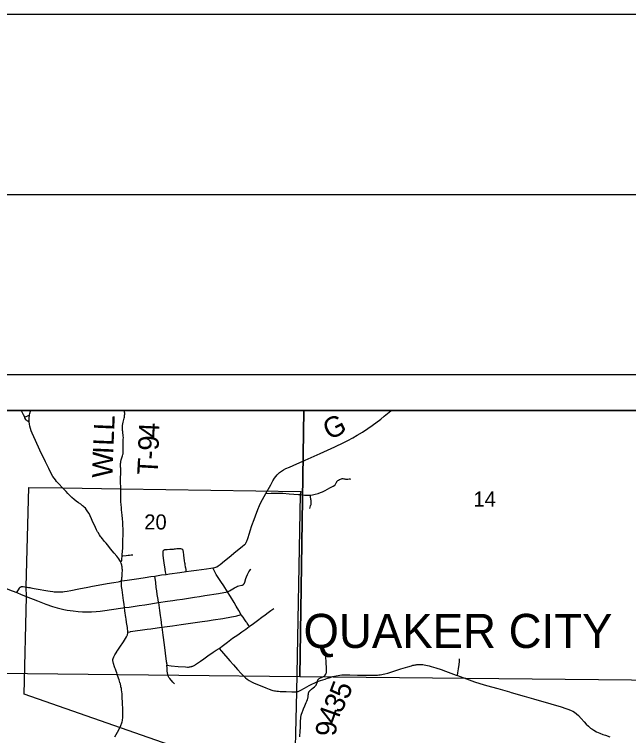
# Model space of a CAD drawing. Extents: x 0 to 34, y 0 to 22.
# Drawn here: x 3.378 to 5.085, y 19.997 to 22 of the extents above; entities that cross this region are included whole.
import ezdxf

# ---------------------------------------------------------------- set-up
doc = ezdxf.new("R2010")
doc.units = 0
for name, color, linetype in [('GM_X_City_Street', 7, 'Continuous'), ('GM_X_Corporation', 7, 'Continuous'), ('GM_X_Corporation_Text', 7, 'Continuous'), ('GM_X_County_Road', 7, 'Continuous'), ('GM_X_County_Road_Text', 7, 'Continuous'), ('GM_X_Section_Text', 7, 'Continuous'), ('GM_X_State_Route', 7, 'Continuous'), ('GM_X_Township_Road', 7, 'Continuous'), ('GM_X_Township_Road_Text', 7, 'Continuous'), ('GM_X_Township_Text', 7, 'Continuous'), ('SH_Border', 7, 'Continuous'), ('SH_Cut_Line', 7, 'Continuous'), ('SH_Data', 7, 'Continuous')]:
    doc.layers.add(name, color=color, linetype=linetype)

msp = doc.modelspace()

# ---------------------------------------------------------------- linework, layer by layer
at = {"layer": 'GM_X_City_Street'}
for points in [[(3.6736, 20.4785), (3.6744, 20.4795), (3.6749, 20.4801), (3.6753, 20.4807), (3.6757, 20.4812), (3.6762, 20.4823), (3.6765, 20.4832), (3.6767, 20.4842), (3.6769, 20.4857), (3.677, 20.4875), (3.6777, 20.4956), (3.6781, 20.5002), (3.6792, 20.5172), (3.6796, 20.5263), (3.6797, 20.5366), (3.6798, 20.5408), (3.6801, 20.5531), (3.6804, 20.5634), (3.6803, 20.5719), (3.6799, 20.5793), (3.6794, 20.5896), (3.6789, 20.5987), (3.6777, 20.6091), (3.6761, 20.6238), (3.6756, 20.628), (3.6747, 20.641), (3.6744, 20.644), (3.6744, 20.6446), (3.6742, 20.649), (3.6742, 20.6564), (3.6743, 20.6613), (3.6744, 20.6644), (3.6744, 20.6668), (3.6743, 20.6702), (3.6742, 20.6725), (3.6741, 20.6749), (3.6741, 20.6766), (3.6739, 20.6818)], [(3.7687, 20.4399), (3.7873, 20.443), (3.7995, 20.4447), (3.8094, 20.4462), (3.8377, 20.4502), (3.8552, 20.4526), (3.8691, 20.4545), (3.8839, 20.4564), (3.9122, 20.46), (3.9239, 20.4616), (3.9296, 20.4625), (3.9306, 20.4626), (3.9354, 20.4637), (3.9382, 20.4646), (3.9409, 20.4659), (3.9445, 20.4681), (3.9499, 20.4722), (3.9625, 20.4823), (3.975, 20.4925), (3.9939, 20.5078), (4.0113, 20.5216), (4.0179, 20.5273), (4.0192, 20.5286), (4.0203, 20.5299), (4.0211, 20.5309), (4.0217, 20.5319), (4.0224, 20.5333), (4.0232, 20.535), (4.0239, 20.5366), (4.0266, 20.5443), (4.0313, 20.5591), (4.0335, 20.5656), (4.0383, 20.5804), (4.0444, 20.5973), (4.0481, 20.6072), (4.0548, 20.6246), (4.0595, 20.6362), (4.0631, 20.6441), (4.0677, 20.6529), (4.0768, 20.6693)], [(4.0768, 20.6693), (4.0917, 20.6701), (4.1029, 20.6705), (4.1128, 20.6705), (4.124, 20.6699), (4.1413, 20.6686), (4.1673, 20.6665), (4.1727, 20.6661)], [(3.7995, 20.4447), (3.7984, 20.4514), (3.796, 20.4653), (3.7954, 20.4698), (3.7944, 20.4767), (3.7929, 20.4894), (3.7919, 20.4981), (3.7916, 20.5024), (3.7915, 20.504), (3.7915, 20.5056), (3.7915, 20.5067), (3.7916, 20.5079), (3.7918, 20.5087), (3.792, 20.5096), (3.7923, 20.5104), (3.7928, 20.5113), (3.7934, 20.512), (3.794, 20.5125), (3.795, 20.5132), (3.796, 20.5135), (3.7978, 20.5138), (3.8027, 20.514), (3.8102, 20.5142), (3.8151, 20.5146), (3.8201, 20.515), (3.8231, 20.5154), (3.8259, 20.5159), (3.8292, 20.5164), (3.8323, 20.5165), (3.8366, 20.5165), (3.8402, 20.5162), (3.8426, 20.5157), (3.8437, 20.5153), (3.8447, 20.5146), (3.8455, 20.5138), (3.846, 20.5128), (3.8464, 20.5111), (3.847, 20.5061), (3.8477, 20.4991), (3.8491, 20.4884), (3.8498, 20.4841), (3.8503, 20.481), (3.8508, 20.4776), (3.8514, 20.4749), (3.8522, 20.471), (3.8531, 20.466), (3.8537, 20.4627), (3.8544, 20.4579), (3.8548, 20.4555), (3.8552, 20.4526)], [(3.6777, 20.4956), (3.6794, 20.4959), (3.6885, 20.497), (3.6947, 20.4977), (3.6983, 20.4982), (3.7027, 20.4988), (3.7071, 20.4993)], [(4.0308, 20.2999), (4.0284, 20.3036), (4.0247, 20.3092), (4.0237, 20.3107), (4.0223, 20.3127), (4.0182, 20.3188), (4.0135, 20.3254), (4.0088, 20.3319), (4.0078, 20.3334), (4.0071, 20.3345), (4.0017, 20.3443), (3.9946, 20.3566), (3.9887, 20.3661), (3.9783, 20.383), (3.9706, 20.3957), (3.9602, 20.4127), (3.9521, 20.4252), (3.9444, 20.4364), (3.939, 20.4447), (3.9349, 20.4516), (3.933, 20.4555), (3.9313, 20.4589), (3.9296, 20.4625)], [(3.9706, 20.3957), (3.9758, 20.3988), (3.9901, 20.4076), (3.9951, 20.4102), (3.9985, 20.4116), (4.0021, 20.4127), (4.0101, 20.4143), (4.0113, 20.4147), (4.0124, 20.4151), (4.0133, 20.4156), (4.014, 20.416), (4.0148, 20.4166), (4.0154, 20.4172), (4.016, 20.4179), (4.0166, 20.4187), (4.0171, 20.4194), (4.0175, 20.4203), (4.0185, 20.4233), (4.0214, 20.4335), (4.0229, 20.4376), (4.0259, 20.4444), (4.0297, 20.4515), (4.0324, 20.4557), (4.0344, 20.4581), (4.0353, 20.459)], [(3.4115, 20.4095), (3.4141, 20.409), (3.4178, 20.4084), (3.4208, 20.4078), (3.4241, 20.4072), (3.4332, 20.4053), (3.4503, 20.4025), (3.4601, 20.4006), (3.4711, 20.3988), (3.478, 20.3977), (3.4852, 20.3968), (3.4889, 20.3965), (3.4932, 20.3962), (3.498, 20.3959), (3.5025, 20.3959), (3.5056, 20.3958), (3.5093, 20.3961), (3.5131, 20.3963), (3.5173, 20.3968), (3.5247, 20.3979), (3.5351, 20.3998), (3.5576, 20.4045), (3.582, 20.4092), (3.5954, 20.4116), (3.6107, 20.4142), (3.6363, 20.419), (3.6547, 20.422), (3.6669, 20.4242), (3.6699, 20.4249), (3.6758, 20.4263), (3.6846, 20.4277), (3.6916, 20.4286), (3.7241, 20.4335), (3.7419, 20.4363), (3.7573, 20.4384), (3.7687, 20.4399)], [(3.7784, 20.3667), (3.7775, 20.3751), (3.7754, 20.3886), (3.7739, 20.3991), (3.7726, 20.4083), (3.7708, 20.4225), (3.7687, 20.4399)], [(3.7784, 20.3667), (3.8032, 20.37), (3.8186, 20.3724), (3.8297, 20.374), (3.8457, 20.3762), (3.8789, 20.3812), (3.893, 20.3834), (3.9071, 20.3855), (3.9458, 20.3913), (3.9706, 20.3957)], [(3.6934, 20.2844), (3.6999, 20.2853), (3.7011, 20.2855), (3.7475, 20.2923), (3.757, 20.2936), (3.7871, 20.2976), (3.7879, 20.2977), (3.8179, 20.3019), (3.8412, 20.3053), (3.8806, 20.3109), (3.8997, 20.3136), (3.9144, 20.3158), (3.9304, 20.3183), (3.9571, 20.3223), (3.9813, 20.3264), (3.9926, 20.3285), (3.9966, 20.3295), (3.9991, 20.3301), (4.0025, 20.3314), (4.0058, 20.3326), (4.0078, 20.3334)], [(3.9473, 20.239), (3.9593, 20.2481), (3.9702, 20.2564), (3.9846, 20.267), (3.9988, 20.2771), (4.0105, 20.2852), (4.0213, 20.2926), (4.0308, 20.2999), (4.0316, 20.3005), (4.0385, 20.3058), (4.0536, 20.3167), (4.0656, 20.3255), (4.0751, 20.3324), (4.0838, 20.3384), (4.0912, 20.3439), (4.099, 20.35)], [(3.8228, 20.1406), (3.8187, 20.1451), (3.8097, 20.1554), (3.8086, 20.1568), (3.8076, 20.1584), (3.8068, 20.1598), (3.8062, 20.1611), (3.8053, 20.163), (3.8048, 20.1646), (3.8042, 20.167), (3.8036, 20.1694), (3.8032, 20.1718), (3.8029, 20.1743), (3.8024, 20.1797), (3.8024, 20.1845), (3.8022, 20.192)]]:
    msp.add_lwpolyline(points, dxfattribs=at)
at = {"layer": 'GM_X_Corporation'}
for points in [[(4.1826, 20.9), (3.1678, 20.9), (3.1616, 20.1718), (4.1713, 20.1609)], [(5.1978, 20.9), (4.1826, 20.9), (4.1713, 20.1609), (5.1859, 20.1511)], [(4.156, 19.8502), (3.4056, 20.1119), (3.4116, 20.3825), (3.4113, 20.41), (3.4183, 20.6864), (3.5128, 20.6849), (3.6737, 20.6823), (4.1737, 20.6751), (4.1725, 20.6666), (4.1618, 20.1184)]]:
    msp.add_lwpolyline(points, close=True, dxfattribs=at)
at = {"layer": 'GM_X_County_Road'}
msp.add_lwpolyline([(4.0768, 20.6693), (4.0904, 20.6938), (4.0963, 20.704), (4.1013, 20.7119), (4.1049, 20.7169), (4.1084, 20.7212), (4.1119, 20.7248), (4.1152, 20.7276), (4.1208, 20.7315), (4.1261, 20.7348), (4.1326, 20.7383), (4.1422, 20.7427), (4.1627, 20.7516), (4.1866, 20.7621), (4.2276, 20.7801), (4.2689, 20.7988), (4.2936, 20.8106), (4.3052, 20.8165), (4.3188, 20.824), (4.3311, 20.8313), (4.3454, 20.8401), (4.3604, 20.8501), (4.372, 20.8584), (4.3961, 20.876), (4.4058, 20.8837), (4.4246, 20.899), (4.4259, 20.9)], dxfattribs=at)
at = {"layer": 'GM_X_State_Route'}
msp.add_line((3.7873, 20.3017), (3.7879, 20.2977), dxfattribs=at)
for points in [[(3.513, 20.6844), (3.5008, 20.6972), (3.4956, 20.7027), (3.4921, 20.707), (3.4888, 20.7116), (3.4854, 20.7169), (3.4799, 20.7266), (3.4736, 20.7388), (3.4647, 20.7573), (3.4493, 20.7899), (3.4367, 20.8169), (3.4277, 20.8367), (3.4249, 20.8437), (3.4226, 20.8502), (3.421, 20.8562), (3.4199, 20.8618), (3.4193, 20.8679), (3.4191, 20.8731), (3.4193, 20.8794), (3.4199, 20.8856), (3.4203, 20.8875), (3.4211, 20.8918), (3.4228, 20.8978), (3.4236, 20.9)], [(3.6764, 20.4315), (3.6769, 20.4356), (3.6773, 20.4387), (3.6775, 20.4413), (3.6777, 20.4439), (3.678, 20.4474), (3.6781, 20.4498), (3.6783, 20.4532), (3.6783, 20.455), (3.6782, 20.4573), (3.6781, 20.4597), (3.678, 20.4612), (3.6779, 20.4628), (3.6778, 20.4637), (3.6777, 20.4645), (3.6775, 20.4654), (3.6774, 20.4662), (3.6771, 20.4678), (3.6769, 20.4686), (3.6767, 20.4694), (3.6764, 20.4709), (3.6763, 20.4717), (3.676, 20.4724), (3.6758, 20.4731), (3.6756, 20.4738), (3.6753, 20.4745), (3.6751, 20.4752), (3.6736, 20.4785), (3.6728, 20.4802), (3.6711, 20.4833), (3.6685, 20.4874), (3.663, 20.4948), (3.6556, 20.504), (3.6456, 20.5159), (3.6408, 20.5216), (3.6365, 20.5268), (3.6329, 20.531), (3.6306, 20.5338), (3.6279, 20.5371), (3.626, 20.5394), (3.623, 20.543), (3.6191, 20.548), (3.6178, 20.5497), (3.6148, 20.5542), (3.611, 20.5605), (3.6094, 20.5632), (3.6065, 20.5687), (3.6035, 20.5749), (3.6013, 20.5799), (3.598, 20.5864), (3.5943, 20.5944), (3.5925, 20.599), (3.589, 20.6069), (3.5857, 20.6135), (3.5826, 20.6188), (3.579, 20.6238), (3.5755, 20.6281), (3.5723, 20.6315), (3.5705, 20.6331), (3.5678, 20.6354), (3.5625, 20.6393), (3.5564, 20.6435), (3.5498, 20.6482), (3.5445, 20.6525), (3.538, 20.6583), (3.5316, 20.6644), (3.5264, 20.6697), (3.5217, 20.6746), (3.5175, 20.6791), (3.513, 20.6844)], [(3.2257, 20.441), (3.2267, 20.4408), (3.2432, 20.438), (3.2659, 20.4341), (3.2768, 20.4319), (3.2901, 20.4288), (3.302, 20.4255), (3.3097, 20.4231), (3.3225, 20.4185), (3.3416, 20.411), (3.3716, 20.3991), (3.3849, 20.394), (3.3975, 20.3888), (3.4094, 20.3838), (3.4109, 20.3833)], [(3.6763, 20.4107), (3.6762, 20.4117), (3.676, 20.4135), (3.6758, 20.4157), (3.6757, 20.4181), (3.6757, 20.4201), (3.6757, 20.4222), (3.6757, 20.4242), (3.6758, 20.4253), (3.6758, 20.4263), (3.676, 20.4284), (3.6764, 20.4315)], [(3.6913, 20.302), (3.69, 20.311), (3.6888, 20.3208), (3.6881, 20.3251), (3.6855, 20.3435), (3.6842, 20.3524), (3.6829, 20.362), (3.6815, 20.3718), (3.6773, 20.402), (3.6763, 20.4107)], [(3.4109, 20.3833), (3.4425, 20.3707), (3.4652, 20.3623), (3.4841, 20.3558), (3.4971, 20.3518), (3.508, 20.3488), (3.5159, 20.3471), (3.5251, 20.3455), (3.5418, 20.3432), (3.5554, 20.3418), (3.5672, 20.341), (3.5797, 20.3408), (3.5838, 20.3408)], [(3.5838, 20.3408), (3.5921, 20.341), (3.6052, 20.3417), (3.617, 20.3428), (3.6299, 20.3445), (3.6484, 20.3471), (3.6797, 20.3517), (3.6842, 20.3524)], [(3.6842, 20.3524), (3.6975, 20.3538), (3.7252, 20.358), (3.7405, 20.3601), (3.7784, 20.3667)], [(3.7784, 20.3667), (3.7804, 20.3517), (3.7814, 20.344), (3.7833, 20.3306), (3.7848, 20.3196), (3.7873, 20.3017)], [(3.6633, 20.2303), (3.6661, 20.2344), (3.6696, 20.2396), (3.6731, 20.2448), (3.675, 20.2476), (3.6776, 20.2517), (3.681, 20.257), (3.6843, 20.2623), (3.6895, 20.2707), (3.6907, 20.2729), (3.6916, 20.275), (3.6923, 20.2767), (3.6928, 20.2783), (3.6933, 20.2806), (3.6934, 20.2821), (3.6934, 20.2836), (3.6934, 20.2844), (3.6933, 20.2861), (3.6931, 20.2884), (3.6926, 20.2929), (3.6921, 20.297), (3.6913, 20.302)], [(3.7879, 20.2977), (3.7908, 20.2758), (3.7942, 20.2487), (3.8002, 20.203), (3.8004, 20.2018), (3.8006, 20.2005), (3.8008, 20.1991)], [(3.8022, 20.192), (3.8139, 20.1902), (3.8331, 20.1886), (3.8536, 20.1874), (3.8593, 20.1872), (3.8618, 20.1873), (3.8646, 20.1876), (3.8671, 20.188), (3.8694, 20.1885), (3.871, 20.1889), (3.8724, 20.1894), (3.8741, 20.19), (3.8755, 20.1906), (3.8793, 20.1926), (3.8819, 20.1944), (3.8951, 20.2037), (3.9042, 20.2102), (3.9158, 20.2185), (3.9307, 20.2286), (3.9391, 20.2339), (3.9473, 20.239)], [(3.9473, 20.239), (3.954, 20.2313), (3.9772, 20.2046), (3.9869, 20.1934), (3.9982, 20.1803), (4.008, 20.1692), (4.0153, 20.1617), (4.0202, 20.1572), (4.0251, 20.1536), (4.0307, 20.15), (4.0372, 20.1464), (4.0444, 20.1429), (4.0563, 20.1378), (4.0768, 20.1293), (4.0865, 20.1255), (4.0935, 20.1232), (4.0967, 20.1223), (4.1006, 20.1214), (4.1041, 20.1208), (4.1079, 20.1203), (4.1125, 20.1199), (4.1171, 20.1197), (4.1332, 20.1192), (4.1487, 20.1188), (4.1567, 20.1188), (4.1596, 20.1188), (4.1611, 20.1188)], [(3.6712, 20.018), (3.6742, 20.0247), (3.6753, 20.0274), (3.6761, 20.0299), (3.6769, 20.0325), (3.6776, 20.0351), (3.6783, 20.0383), (3.6789, 20.0417), (3.6793, 20.045), (3.6794, 20.0478), (3.6796, 20.0514), (3.6796, 20.0545), (3.6792, 20.0699), (3.6785, 20.0873), (3.678, 20.1046), (3.6775, 20.1127), (3.6768, 20.1188), (3.676, 20.1241), (3.6754, 20.1274), (3.6744, 20.1327), (3.6738, 20.1361), (3.6734, 20.138), (3.673, 20.1398), (3.6727, 20.1409), (3.6723, 20.1419), (3.6714, 20.1445), (3.6689, 20.1516), (3.665, 20.1633), (3.6625, 20.1709), (3.661, 20.1756), (3.659, 20.1814), (3.6576, 20.1854), (3.6567, 20.188), (3.6537, 20.1967), (3.6532, 20.1983), (3.6529, 20.1998), (3.6526, 20.2015), (3.6522, 20.2034), (3.6521, 20.2047), (3.652, 20.2061), (3.6521, 20.2073), (3.6522, 20.2087), (3.6525, 20.2101), (3.653, 20.2117), (3.6535, 20.2132), (3.6543, 20.2152), (3.6553, 20.2172), (3.6563, 20.2193), (3.6576, 20.2216), (3.6592, 20.2242), (3.6628, 20.2295), (3.6633, 20.2303)], [(3.8008, 20.1991), (3.8011, 20.1973), (3.8014, 20.196), (3.8017, 20.1942), (3.8022, 20.192)], [(4.1611, 20.1188), (4.1623, 20.1189), (4.1645, 20.1191), (4.1669, 20.1195), (4.1689, 20.1202), (4.1709, 20.121), (4.1726, 20.1218), (4.174, 20.1226), (4.1842, 20.1286), (4.1977, 20.1363), (4.2043, 20.1398), (4.2128, 20.1437), (4.2203, 20.1468), (4.2285, 20.1498), (4.2415, 20.154), (4.2503, 20.1568), (4.2533, 20.1577), (4.2634, 20.1606), (4.2724, 20.163), (4.2776, 20.1641), (4.2828, 20.1648), (4.2881, 20.1653), (4.294, 20.1655), (4.3103, 20.1654), (4.3314, 20.1647), (4.3376, 20.1646), (4.3487, 20.1645), (4.371, 20.1644), (4.3834, 20.1647), (4.3873, 20.165), (4.3913, 20.1653), (4.3948, 20.1657), (4.3993, 20.1664), (4.4032, 20.1672), (4.4071, 20.168), (4.4161, 20.1704), (4.4297, 20.1745), (4.4521, 20.1819), (4.4711, 20.1879), (4.4819, 20.191), (4.4856, 20.192), (4.4892, 20.1928), (4.4919, 20.1934), (4.4947, 20.1938), (4.4968, 20.1941), (4.4991, 20.1943), (4.5019, 20.1945), (4.5048, 20.1945), (4.5071, 20.1944), (4.5104, 20.1942), (4.5136, 20.1939), (4.5173, 20.1933), (4.5218, 20.1924), (4.5265, 20.1914), (4.5311, 20.1903), (4.5361, 20.1889), (4.5493, 20.185), (4.564, 20.1801), (4.5763, 20.1757), (4.6054, 20.1648), (4.6095, 20.1633), (4.6347, 20.1542), (4.6569, 20.1464), (4.6711, 20.1419), (4.6902, 20.1364), (4.7219, 20.1274), (4.7535, 20.1182), (4.7588, 20.1166), (4.7947, 20.1064), (4.821, 20.0989), (4.8687, 20.0848), (4.8973, 20.0765), (4.9104, 20.0723), (4.9192, 20.0691), (4.925, 20.0667), (4.9295, 20.0644), (4.9343, 20.0615), (4.9399, 20.0573), (4.9454, 20.0522), (4.953, 20.0439), (4.9613, 20.0347), (4.9673, 20.0285), (4.9736, 20.0226), (4.9793, 20.0179), (4.9828, 20.0154), (4.9885, 20.0117), (4.9961, 20.0076), (5.0045, 20.0037), (5.0131, 20.0002), (5.0207, 19.9976), (5.0332, 19.9938)], [(3.6573, 19.993), (3.661, 19.9998), (3.6645, 20.0061), (3.6712, 20.018)]]:
    msp.add_lwpolyline(points, dxfattribs=at)
at = {"layer": 'GM_X_Township_Road'}
for points in [[(3.4068, 20.8809), (3.4034, 20.8874), (3.3976, 20.8991), (3.3971, 20.9)], [(3.6739, 20.6818), (3.6738, 20.6853), (3.6734, 20.7013), (3.6733, 20.7042), (3.6734, 20.7075), (3.6735, 20.7124), (3.6735, 20.7161), (3.6736, 20.7209), (3.6737, 20.7277), (3.6738, 20.7326), (3.6737, 20.7345), (3.6737, 20.7369), (3.6736, 20.7398), (3.6734, 20.7425), (3.6734, 20.7455), (3.6733, 20.7485), (3.6734, 20.7507), (3.6735, 20.7529), (3.6736, 20.7552), (3.674, 20.7576), (3.6744, 20.76), (3.6747, 20.7615), (3.6752, 20.7631), (3.676, 20.7658), (3.6778, 20.7709), (3.6788, 20.7742), (3.6798, 20.7774), (3.6804, 20.7799), (3.6807, 20.7823), (3.6809, 20.7847), (3.6809, 20.7873), (3.6807, 20.7972), (3.6806, 20.8034), (3.6806, 20.809), (3.6809, 20.8189), (3.681, 20.8245), (3.6809, 20.8282), (3.6807, 20.8306), (3.6796, 20.8384), (3.6792, 20.8411), (3.6789, 20.8444), (3.6785, 20.8478), (3.6783, 20.851), (3.6783, 20.854), (3.6784, 20.8564), (3.6786, 20.8583), (3.6793, 20.8625), (3.6803, 20.8674), (3.6831, 20.8782), (3.6839, 20.8816), (3.6843, 20.8843), (3.6846, 20.8873), (3.6847, 20.8898), (3.6847, 20.8924), (3.6845, 20.8948), (3.684, 20.8978), (3.6836, 20.9)], [(3.4203, 20.8875), (3.418, 20.886), (3.4163, 20.8849), (3.4141, 20.8837), (3.4125, 20.883), (3.4102, 20.8821), (3.4068, 20.8809)], [(3.4193, 20.8679), (3.4181, 20.8686), (3.4154, 20.8699), (3.4143, 20.8705), (3.4128, 20.8716), (3.4114, 20.8731), (3.4102, 20.8748), (3.4074, 20.8797), (3.4068, 20.8809)], [(4.2001, 20.6649), (4.2021, 20.665), (4.2063, 20.6656), (4.2136, 20.6673), (4.2226, 20.6696), (4.2285, 20.6716), (4.2348, 20.6743), (4.242, 20.678), (4.255, 20.6853), (4.2567, 20.6861), (4.2637, 20.69), (4.2684, 20.6924), (4.2697, 20.6936), (4.2708, 20.695), (4.2716, 20.6967), (4.2725, 20.6986), (4.273, 20.6996), (4.2734, 20.7006), (4.2739, 20.7017), (4.2745, 20.7027), (4.2752, 20.7036), (4.276, 20.7045), (4.2768, 20.7052), (4.2788, 20.7063), (4.282, 20.7078), (4.2842, 20.7089), (4.287, 20.7101), (4.2894, 20.7106), (4.2913, 20.7106), (4.2937, 20.7104), (4.2961, 20.7099), (4.2984, 20.7093), (4.3015, 20.7092), (4.3052, 20.7095), (4.3082, 20.7099), (4.3101, 20.7099), (4.3118, 20.7094)], [(4.1727, 20.6661), (4.1844, 20.665), (4.1917, 20.6647), (4.1972, 20.6647), (4.2001, 20.6649)], [(4.1988, 20.6275), (4.2002, 20.6316), (4.2012, 20.6348), (4.2019, 20.6375), (4.2024, 20.6389), (4.2025, 20.6397), (4.2026, 20.6405), (4.2027, 20.6414), (4.2027, 20.6423), (4.2028, 20.6434), (4.2028, 20.6442), (4.2027, 20.6453), (4.2027, 20.6465), (4.2025, 20.6486), (4.2024, 20.6504), (4.2022, 20.6516), (4.2021, 20.6529), (4.2018, 20.6545), (4.2017, 20.6558), (4.2014, 20.6575), (4.2011, 20.6591), (4.2008, 20.6605), (4.2006, 20.6621), (4.2001, 20.6649)], [(3.3849, 20.394), (3.392, 20.4064), (3.3928, 20.4074), (3.3936, 20.4083), (3.3943, 20.409), (3.395, 20.4095), (3.3958, 20.41), (3.3966, 20.4104), (3.3974, 20.4107), (3.3984, 20.411), (3.3992, 20.4111), (3.4002, 20.4112), (3.4014, 20.4112), (3.4027, 20.411), (3.4115, 20.4095)], [(4.2203, 20.1468), (4.2205, 20.1485), (4.221, 20.1501), (4.2218, 20.1518), (4.2226, 20.1528), (4.2235, 20.1539), (4.2241, 20.1545), (4.2249, 20.155), (4.2269, 20.1559), (4.2336, 20.1587), (4.2368, 20.1606), (4.2397, 20.1629), (4.2419, 20.1651), (4.2437, 20.1676), (4.2448, 20.1698), (4.2455, 20.1722), (4.2458, 20.1759), (4.2456, 20.1827), (4.2446, 20.2018), (4.244, 20.2148), (4.2434, 20.2209), (4.243, 20.2239), (4.2421, 20.2275), (4.2407, 20.2316), (4.2391, 20.2363), (4.2384, 20.2393)], [(4.6095, 20.1633), (4.6107, 20.1708), (4.6124, 20.1826), (4.614, 20.1943), (4.6151, 20.2024), (4.6153, 20.2043), (4.6153, 20.2061), (4.615, 20.2092), (4.6149, 20.2098)], [(4.1717, 19.9934), (4.1725, 20.0101), (4.1728, 20.0181), (4.1731, 20.0255), (4.1732, 20.028), (4.1734, 20.0367), (4.1739, 20.0453), (4.1742, 20.0476), (4.1745, 20.0501), (4.1749, 20.052), (4.1751, 20.0529), (4.1753, 20.0538), (4.1754, 20.0544), (4.1758, 20.0556), (4.1763, 20.0573), (4.1767, 20.0585), (4.1814, 20.0707), (4.1853, 20.0799), (4.1871, 20.0838), (4.1889, 20.0884), (4.1906, 20.0923), (4.1924, 20.0969), (4.1929, 20.0984), (4.1933, 20.0997), (4.1937, 20.1008), (4.1939, 20.102), (4.1943, 20.1039), (4.1947, 20.1068), (4.1949, 20.1098), (4.195, 20.1108), (4.1951, 20.1118), (4.1952, 20.1129), (4.1954, 20.114), (4.1956, 20.1148), (4.1958, 20.1155), (4.196, 20.1162), (4.1963, 20.1169), (4.1967, 20.118), (4.1974, 20.1191), (4.1981, 20.1201), (4.1989, 20.121), (4.1994, 20.1216), (4.1999, 20.1221), (4.2005, 20.1227), (4.201, 20.1232), (4.2025, 20.1244), (4.2037, 20.1254), (4.2086, 20.1294), (4.2124, 20.1326), (4.2145, 20.1349), (4.2155, 20.1361), (4.2163, 20.1373), (4.2177, 20.1399), (4.2188, 20.142), (4.2196, 20.1436), (4.2199, 20.1442), (4.2202, 20.145), (4.2202, 20.1458), (4.2203, 20.1468)]]:
    msp.add_lwpolyline(points, dxfattribs=at)
at = {"layer": 'GM_X_Township_Text'}
msp.add_lwpolyline([(7.231, 20.9), (2.1, 20.9), (2.1, 19.1775)], dxfattribs=at)
at = {"layer": 'SH_Border'}
msp.add_lwpolyline([(1.5, 21.5), (33.5, 21.5), (33.5, 0.5), (1.5, 0.5)], close=True, dxfattribs=at)
at = {"layer": 'SH_Cut_Line'}
msp.add_lwpolyline([(0, 0), (34, 0), (34, 22), (0, 22)], close=True, dxfattribs=at)
at = {"layer": 'SH_Data'}
for p, q in [((2, 21), (9, 21)), ((2.1, 20.9), (8.9, 20.9))]:
    msp.add_line(p, q, dxfattribs=at)

# ---------------------------------------------------------------- texts
at = {"layer": 'GM_X_Corporation_Text'}
msp.add_text('QUAKER CITY', height=0.094697, rotation=0, dxfattribs=at).set_placement((4.1816, 20.2402))
at = {"layer": 'GM_X_County_Road_Text'}
msp.add_text('G', height=0.0568, rotation=26.9234, dxfattribs=at).set_placement((4.2537, 20.8164))
at = {"layer": 'GM_X_Section_Text'}
for s, p in [('14', (4.6537, 20.633)), ('20', (3.7391, 20.5693))]:
    msp.add_text(s, height=0.04186, rotation=0, dxfattribs=at).set_placement(p)
at = {"layer": 'GM_X_Township_Road_Text'}
for s, rotation, p in [('L', 87.5437, (3.6555, 20.8435)), ('4', 87.2774, (3.7795, 20.8226)), ('L', 87.5436, (3.6537, 20.8011)), ('9', 89.6631, (3.7793, 20.7883)), ('I', 87.5715, (3.6527, 20.7778)), ('W', 88.4671, (3.651, 20.7122)), ('-', 87.7699, (3.7784, 20.7629)), ('T', 86.784, (3.7759, 20.7194)), ('5', 69.2873, (4.3049, 20.0946)), ('3', 60.7134, (4.2839, 20.0557)), ('4', 70.2419, (4.2731, 20.025)), ('9', 86.7927, (4.272, 19.9943))]:
    msp.add_text(s, height=0.0568, rotation=rotation, dxfattribs=at).set_placement(p)

doc.saveas('drawing.dxf')
